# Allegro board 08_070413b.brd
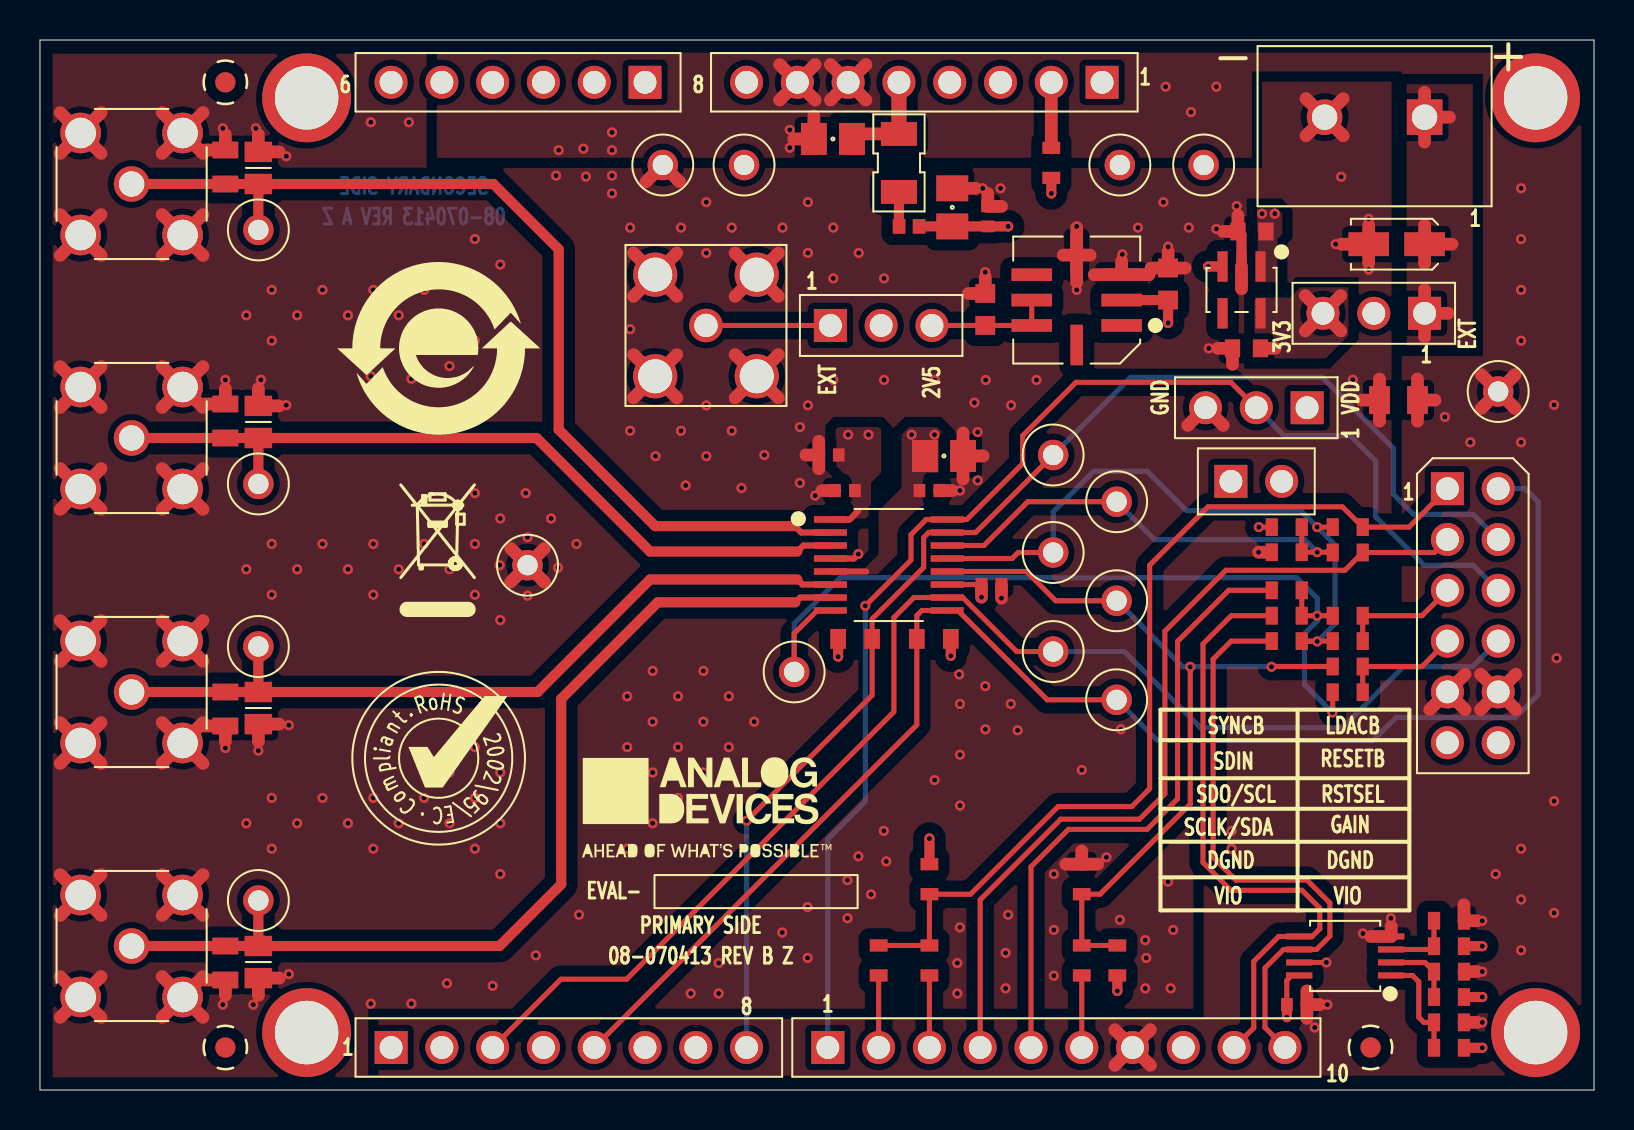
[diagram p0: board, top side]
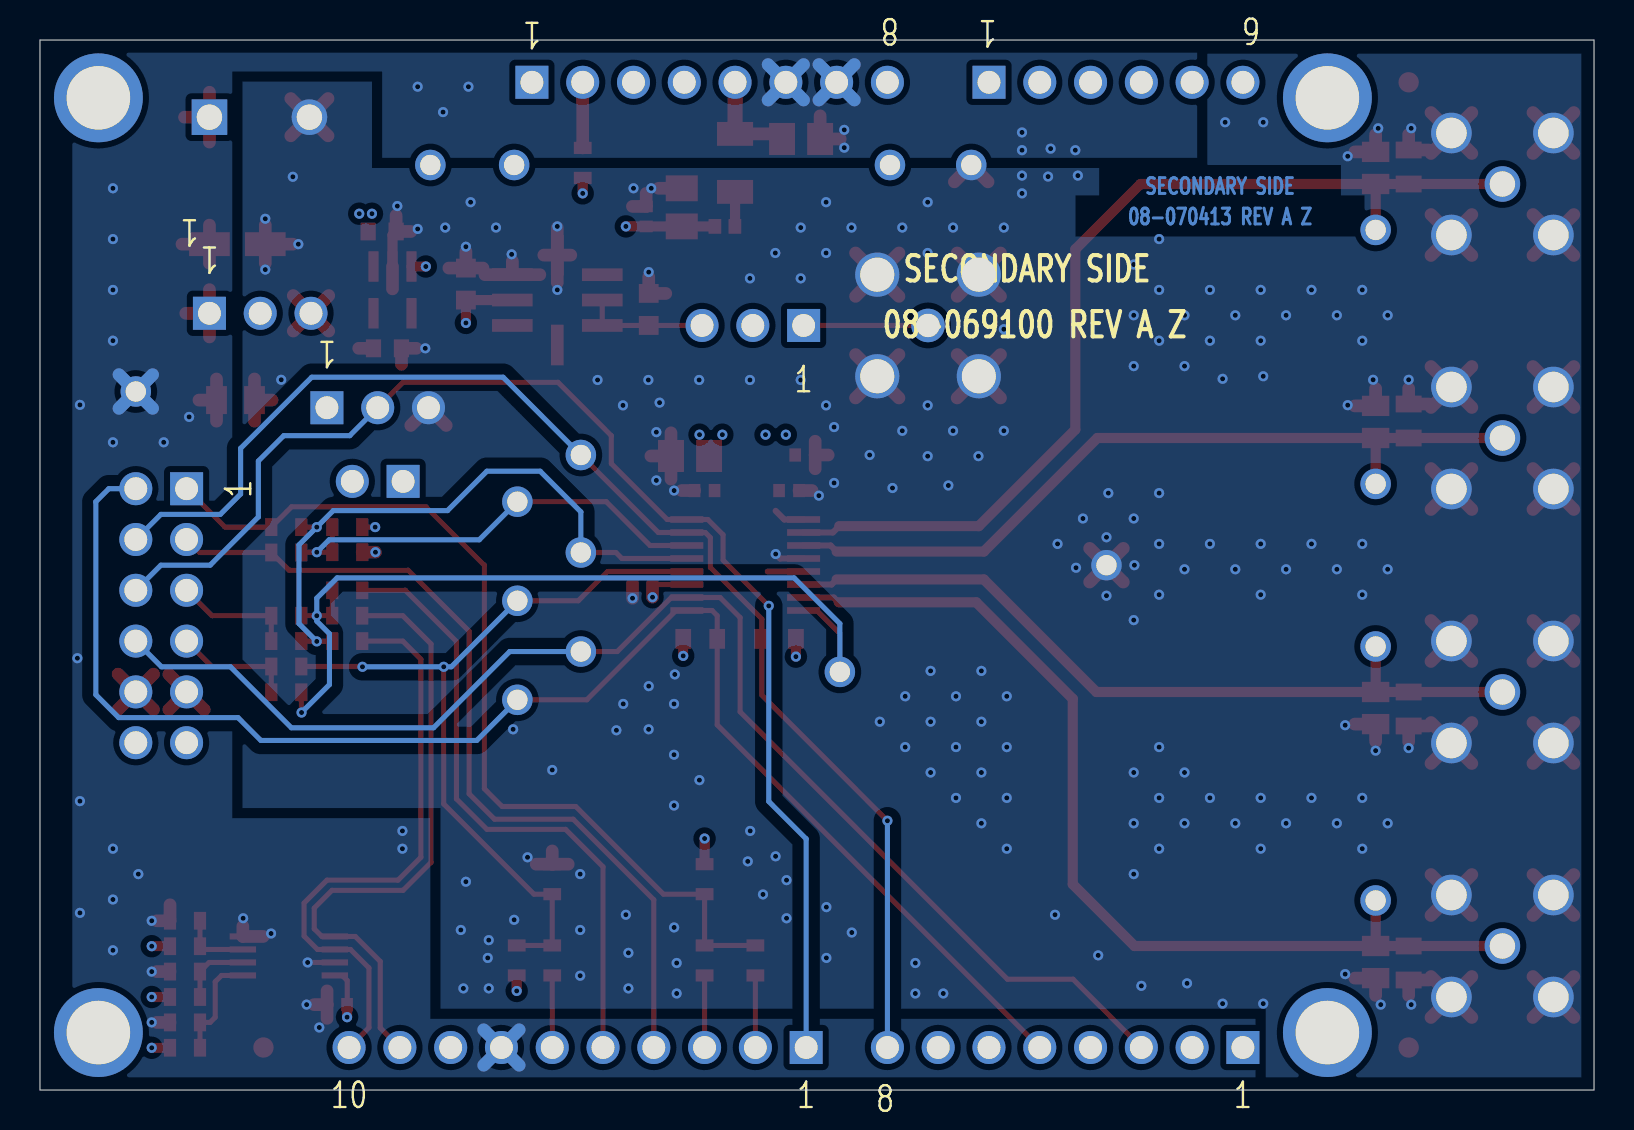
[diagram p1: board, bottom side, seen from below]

Outline 77.72 x 52.5 mm; copper layers: TOP, L2_GND, L3_PWR, BOTTOM. Coordinates in mm from the lower left corner of the outline.
Outline path: 0,52.5 77.72,52.5 77.72,0 0,0 0,52.5

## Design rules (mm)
constraint set DEFAULT: min track width 0.254

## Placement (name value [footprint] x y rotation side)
AGND  BLK  [CNKEY5001TP]  31.15 46.25 0 top
AGND1  BLK  [CNKEY5001TP]  24.38 26.24 0 top
C1  0.1uF  [C0402]  62.86 4.27 180 top
C2  10uF  [C0805H60]  39.66 47.55 180 top
C3  4.7uF  [C0805H60]  45.63 44.13 90 top
C4  0.1uF  [C0402]  47.41 43.68 90 top
C5  1uF  [C0603#2]  60.61 42.93 180 top
C6  0.1uF  [C0402]  44.48 29.97 0 top
C7  10uF  [C0805H60]  45.21 31.7 180 top
C8  10uF  [C3216]  67.85 42.29 180 top
C9  0.1uF  [C0402]  40.26 29.97 180 top
C10  0.1uF  [C0402]  39.45 31.75 180 top
C11  1uF  [C0603#2]  60.34 37.08 180 top
C12  0.1uF  [C0402]  47.59 25.27 0 top
C13  200pF  [C0805]  10.92 19.1 270 top
C14  200pF  [C0805]  10.92 33.4 90 top
C15  0.1uF  [C0603]  56.42 40.3 90 top
C16  200pF  [C0805]  10.92 46.1 90 top
C17  200pF  [C0805]  10.92 6.4 270 top
C18  1uF  [C0603]  47.28 39.03 90 top
DGND  BLK  [CNKEY5001TP]  72.93 34.92 0 top
E1  600OHM  [L1206H71]  42.96 46.35 270 top
EXT_REF  131-3701-261  [CNJOHNSON131-3701-261]  33.31 38.23 90 top
EXT_VDD  691102710002  [CNWURTH691102710002]  69.25 48.64 180 top
GAIN  WHT  [CNKEY5001TP]  50.67 21.92 0 top
LDACB  WHT  [CNKEY5001TP]  53.85 19.51 0 top
NOREF  -  []  77.72 0 0 top
NOREF#2  -  []  33.05 14.1 0 top
NOREF#3  -  []  217.08 56.1 0 top
NOREF#4  -  []  37.34 9.09 0 top
NOREF#5  -  []  19.68 23.71 0 top
NOREF#6  -  []  77.72 0 90 top
NOREF#7  -  []  -40.99 233.9 0 top
NOREF#8  -  []  0 0 0 top
NOREF#9  -  []  77.72 52.53 180 top
NOREF#10  -  []  0 0 0 top
NOREF#11  -  []  19.94 37.08 0 top
NOREF#12  -  []  0 52.5 270 top
NOREF#13  -  []  2.03 4.65 0 top
NOREF#14  -  []  0 52.5 0 top
NOREF#15  -  []  -68.29 -166.91 0 top
NOREF#16  -  [unnamed#2]  13.34 49.61 0 top
NOREF#17  -  []  -69.82 -166.91 0 top
NOREF#18  -  [unnamed#2]  74.8 2.87 0 top
NOREF#19  -  [unnamed#2]  74.8 49.61 0 top
NOREF#20  -  []  79.41 90.77 0 top
NOREF#21  -  []  0 52.5 0 top
NOREF#22  -  [unnamed#2]  66.55 2.12 0 top
NOREF#23  -  []  158.53 157.95 0 top
NOREF#24  -  []  19.94 16.59 0 top
NOREF#25  -  []  2.03 4.65 0 top
NOREF#26  -  [unnamed#2]  9.27 50.38 0 top
NOREF#27  -  []  77.72 0 90 top
NOREF#28  -  []  0 0 0 top
NOREF#29  -  []  -69.05 -166.91 0 top
NOREF#30  -  []  43.57 69.82 0 top
NOREF#31  -  [unnamed#2]  13.34 2.87 0 top
NOREF#32  -  [unnamed#2]  9.27 2.12 0 top
P3  SSQ-108-03-G-S  [CNSAMTECSSQ-108-XX-X-S]  53.12 50.38 180 top
P4  SSQ-106-03-G-S  [CNSAMTECSSQ-106-XX-X-S]  30.26 50.38 180 top
P6  SSQ-110-03-G-S  [CNSAMTECSSQ-110-XX-X-S]  39.4 2.12 0 top
P7  SSQ-108-03-G-S  [CNSAMTECSSQ-108-XX-X-S]  17.56 2.12 0 top
PMOD  TSW-106-08-G-D  [CNHDR2X6H330LD35]  70.39 30.06 270 top
R1  100K  [R0603]  70.47 7.19 180 top
R2  100K  [R0603]  70.47 5.92 0 top
R3  0  [R0805]  67.94 34.49 180 top
R4  100K  [R0603]  70.47 2.11 180 top
R5  0  [R0603]  50.58 46.35 270 top
R6  1.8  [R0402]  43.47 43.18 0 top
R7  100K  [R0603]  44.48 10.54 270 top
R8  100K  [R0603]  70.47 8.46 0 top
R9  100K  [R0603]  70.47 4.65 180 top
R10  0  [R0603]  44.48 6.48 270 top
R11  0  [R0603]  41.94 6.48 270 top
R12  100K  [R0603]  70.47 3.38 0 top
R13  2.0K  [R0805#2]  9.27 19.05 270 top
R14  2.0K  [R0805#2]  9.27 33.45 90 top
R15  2.0K  [R0805#2]  9.27 46.15 90 top
R16  2.0K  [R0805#2]  9.27 6.35 270 top
R17  0  [R0603]  62.36 24.98 0 top
R18  0  [R0603]  62.36 23.71 0 top
R19  0  [R0603]  65.41 19.89 180 top
R20  0  [R0603]  65.41 23.71 180 top
R21  0  [R0603]  65.41 26.87 180 top
R22  0  [R0603]  62.36 28.14 0 top
R23  0  [R0603]  62.36 26.89 0 top
R24  0  [R0603]  65.41 28.14 180 top
R25  0  [R0603]  62.36 22.44 0 top
R26  0  [R0603]  65.41 22.44 180 top
R27  0  [R0603]  52.1 6.48 90 top
R28  0  [R0603]  65.41 21.17 180 top
R29  0  [R0603]  53.88 6.48 90 top
R30  0  [R0603]  52.1 10.54 270 top
R31  100K  [R0603]  44.7 22.56 180 top
R32  100K  [R0603]  40.77 22.56 0 top
REF_SEL  YMC03SAAN  [CNTHMHDR1X3L300W100H343_A]  39.53 38.23 0 top
RESETB  WHT  [CNKEY5001TP]  50.67 31.75 0 top
RSTSEL  YMC03SAAN  [CNTHMHDR1X3L300W100H343_A]  63.37 34.11 180 top
SCLK/A0  WHT  [CNKEY5001TP]  53.85 24.46 180 top
SDIN/A1  WHT  [CNKEY5001TP]  53.85 29.41 0 top
SDO/SDA  WHT  [CNKEY5001TP]  37.72 20.91 0 top
SYNCB/SCL  WHT  [CNKEY5001TP]  50.67 26.87 180 top
U1  AD5686RBRUZ  [TSSOP16]  42.45 26.25 270 top
U2  ADP121-AUJZ33  [TSOT-5]  60.09 40 180 top
U3  ADR4525DEZ  [LCC8]  51.85 39.5 90 top
U4  24LC32A-I/MS  [MSOP8]  65.28 6.7 90 top
VDD  RED  [CNKEY5001TP]  58.2 46.25 0 top
VDD_SEL  YMC03SAAN  [CNTHMHDR1X3L300W100H343_A]  69.25 38.84 180 top
VDD_VIO  M20-9990245  [CNHARWIN-M20-9990246]  59.56 30.43 0 top
VLOGIC  RED  [CNKEY5001TP]  54.01 46.25 0 top
VOUT_A  1-1337482-0  [CNBNCSQ276H299]  4.58 32.6 0 top
VOUT_B  1-1337482-0  [CNBNCSQ276H299]  4.58 45.3 0 top
VOUT_C  1-1337482-0  [CNBNCSQ276H299]  4.58 19.9 0 top
VOUT_D  1-1337482-0  [CNBNCSQ276H299]  4.58 7.2 0 top
VOUTA  RED  [CNKEY5001TP]  10.92 30.3 0 top
VOUTB  RED  [CNKEY5001TP]  10.92 43 0 top
VOUTC  RED  [CNKEY5001TP]  10.92 22.18 0 top
VOUTD  RED  [CNKEY5001TP]  10.92 9.48 0 top
VREF  RED  [CNKEY5001TP]  35.21 46.25 90 top

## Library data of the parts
AGND DGND = CNTP1P: Tolerance: N/A; User Part Number: UPN; alternate symbols: (); part number: CNTP1P_TH-BLK,E005347,CNKEY5001TP; tolerance: N/A
AGND1 = CNTP1P: Tolerance: N/A; User Part Number: UPN; alternate symbols: (); part number: CNTP1P_TH-BLK,E019484,CNKEY5001TP; tolerance: N/A
C1 = CAP: User Part Number: UPN; Tolerance: 10; alternate symbols: (C0402L); part number: CAP_SM-0.1UF,16V,10,E028141,C0402; tolerance: 10
C2 C7 = CAP: Tolerance: 10; User Part Number: UPN; alternate symbols: (); part number: CAP_SM-10UF,25V,10,E014704,C0805H60; tolerance: 10
C3 = CAP: Tolerance: 10; User Part Number: UPN; alternate symbols: (); part number: CAP_SM-4.7UF,25V,10,E024738,C0805H60; tolerance: 10
C4 C6 C9 C10 C12 = CAP: User Part Number: UPN; Tolerance: 10; alternate symbols: (C0402L); part number: CAP_SM-0.1UF,16V,10,E018707,C0402; tolerance: 10
C5 C11 C18 = CAP: User Part Number: UPN; Tolerance: 10; alternate symbols: (C0603L); part number: CAP_SM-1UF,16V,10,E020111,C0603; tolerance: 10
C8 = CAPP: Tolerance: 10; User Part Number: UPN; alternate symbols: (); part number: CAPP_SM-10UF,10V,10,E011061,C3216; tolerance: 10
C13 C14 C16 C17 = CAP: User Part Number: UPN; Tolerance: 5; alternate symbols: (C0805L); part number: CAP_SM-200PF,16V,5,E034930,C0805; tolerance: 5
C15 = CAP: User Part Number: UPN; Tolerance: 10; alternate symbols: (C0603L); part number: CAP_SM-0.1UF,50V,10,E031401,C0603; tolerance: 10
E1 = FERRITE: User Part Number: UPN; Tolerance: 25; alternate symbols: (); part number: FERRITE_SM-600OHM,25,E048457,L1206H71; tolerance: 25
EXT_REF = CNBNC5P: Tolerance: N/A; User Part Number: UPN; alternate symbols: (); part number: CNBNC5P_TH-131-3701-261,E012123,CNJOHNSON131-3701-261; tolerance: N/A
EXT_VDD = CN2P: Tolerance: N/A; User Part Number: UPN; alternate symbols: (); part number: CN2P_TH-691102710002,E048111,CNWURTH691102710002; tolerance: N/A
GAIN LDACB RESETB SCLK/A0 SDIN/A1 SDO/SDA SYNCB/SCL = CNTP1P: Tolerance: N/A; User Part Number: UPN; alternate symbols: (); part number: CNTP1P_TH-WHT,E006153,CNKEY5001TP; tolerance: N/A
P3 P7 = CN8P_A: User Part Number: UPN; Tolerance: N/A; alternate symbols: (); part number: CN8P_A_TH-SSQ-108-03-G-S,E020478,CNSAMTECSSQ-108-XX-X-S; tolerance: N/A
P4 = CN6P: User Part Number: UPN; Tolerance: N/A; alternate symbols: (); part number: CN6P_TH-SSQ-106-03-G-S,E020477,CNSAMTECSSQ-106-XX-X-S; tolerance: N/A
P6 = CN10P: User Part Number: UPN; Tolerance: N/A; alternate symbols: (); part number: CN10P_TH-SSQ-110-03-G-S,E020479,CNSAMTECSSQ-110-XX-X-S; tolerance: N/A
PMOD = CN12P_V3: Tolerance: N/A; User Part Number: UPN; alternate symbols: (); part number: CN12P_V3_TH-TSW-106-08-G-D,E000735,CNHDR2X6H330LD35; tolerance: N/A
R1 R2 R4 R7-R9 R12 R31 R32 = RES: User Part Number: UPN; Tolerance: 1; alternate symbols: (R0603L); part number: RES_SM-100K,E018430,1/16W,1,R0603; tolerance: 1
R3 = RES: User Part Number: UPN; Tolerance: JUMPER; alternate symbols: (R0805L); part number: RES_SM-0,E030875,1/8W,JUMPER,R0805; tolerance: JUMPER
R5 R10 R11 R17-R30 = RES: User Part Number: UPN; Tolerance: JUMPER; alternate symbols: (R0603L); part number: RES_SM-0,E054377,1/10W,JUMPER,R0603; tolerance: JUMPER
R6 = RES: User Part Number: UPN; Tolerance: 5; alternate symbols: (R0402L); part number: RES_SM-1.8,E016361,1/10W,5,R0402; tolerance: 5
R13-R16 = RES: User Part Number: UPN; Tolerance: 0.1; alternate symbols: (R0805L); part number: RES_SM-2.0K,E003813,1/8W,0.1,R0805; tolerance: 0.1
REF_SEL RSTSEL VDD_SEL = CN3P_JMPRSHRT: User Part Number: UPN; Tolerance: N/A; alternate symbols: (); part number: CN3P_JMPRSHRT_TH-YMC03SAAN,E030075,CNTHMHDR1X3L300W100H343_A; tolerance: N/A
U1 = AD568XR_V4: Tolerance: N/A; User Part Number: UPN; alternate symbols: (); part number: AD568XR_V4_SM-AD5686RBRUZ,E012461,TSSOP16; tolerance: N/A
U2 = ADP121: User Part Number: UPN; Tolerance: N/A; alternate symbols: (); part number: ADP121_SM-ADP121-AUJZ33,E013943,TSOT-5; tolerance: N/A
U3 = ADR45XX_V2: User Part Number: UPN; Tolerance: N/A; alternate symbols: (); part number: ADR45XX_V2_SM-ADR4525DEZ,E055648,LCC8; tolerance: N/A
U4 = IC24FC256: Tolerance: N/A; User Part Number: UPN; alternate symbols: (); part number: IC24FC256_SM-24LC32A-I/MS,E014160,MSOP8; tolerance: N/A
VDD VLOGIC VOUTA VOUTB VOUTC VOUTD VREF = CNTP1P: Tolerance: N/A; User Part Number: UPN; alternate symbols: (); part number: CNTP1P_TH-RED,E016323,CNKEY5001TP; tolerance: N/A
VDD_VIO = CN2P: Tolerance: N/A; User Part Number: UPN; alternate symbols: (); part number: CN2P_TH-M20-9990245,E019487,CNHARWIN-M20-9990246; tolerance: N/A
VOUT_A VOUT_B VOUT_C VOUT_D = CNBNC5P: Tolerance: N/A; User Part Number: UPN; alternate symbols: (); part number: CNBNC5P_TH-1-1337482-0,E013941,CNBNCSQ276H299; tolerance: N/A

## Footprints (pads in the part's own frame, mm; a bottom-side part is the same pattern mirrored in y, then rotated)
C0402
  rect 0.584x0.66 smd: 1(-0.5,0) 2(0.5,0)
C0603
  rect 0.94x0.991 smd: 1(-0.8,0) 2(0.8,0)
C0603#2
  rect 0.762x0.889 smd: 1(-0.7,0) 2(0.7,0)
C0805
  rect 1.016x1.372 smd: 1(-0.803,0) 2(0.803,0)
C0805H60
  rect 1.295x1.6 smd: 1(-0.953,0) 2(0.953,0)
C3216
  rect 2.032x1.194 smd: N(1.397,0) P(-1.397,0)
CNBNCSQ276H299
  round 1.778 hole 1.27: 1(0,0)
  round 2.032 hole 1.524: 2(-2.55,2.55) 3(2.55,2.55) 4(2.55,-2.55) 5(-2.55,-2.55)
CNHARWIN-M20-9990246
  rect 1.651x1.651 hole 1.143: 1(0,0)
  round 1.651 hole 1.143: 2(2.54,0)
CNHDR2X6H330LD35
  rect 1.651x1.651 hole 1.143: 1(0,0)
  round 1.651 hole 1.143: 2(2.54,0) 3(5.08,0) 4(7.62,0) 5(10.16,0) 6(12.7,0) 7(0,2.54) 8(2.54,2.54) 9(5.08,2.54) 10(7.62,2.54) 11(10.16,2.54) 12(12.7,2.54)
CNJOHNSON131-3701-261
  round 1.676 hole 1.168: 1(0,0)
  round 2.21 hole 1.702: 2(-2.54,2.54) 3(2.54,2.54) 4(2.54,-2.54) 5(-2.54,-2.54)
CNKEY5001TP
  round 1.524 hole 1.016: 1(0,0)
CNSAMTECSSQ-106-XX-X-S
  rect 1.651x1.651 hole 1.143: 1(0,0)
  round 1.651 hole 1.143: 2(2.54,0) 3(5.08,0) 4(7.62,0) 5(10.16,0) 6(12.7,0)
CNSAMTECSSQ-108-XX-X-S
  rect 1.651x1.651 hole 1.143: 1(0,0)
  round 1.651 hole 1.143: 2(2.54,0) 3(5.08,0) 4(7.62,0) 5(10.16,0) 6(12.7,0) 7(15.24,0) 8(17.78,0)
CNSAMTECSSQ-110-XX-X-S
  rect 1.651x1.651 hole 1.143: 1(0,0)
  round 1.651 hole 1.143: 2(2.54,0) 3(5.08,0) 4(7.62,0) 5(10.16,0) 6(12.7,0) 7(15.24,0) 8(17.78,0) 9(20.32,0) 10(22.86,0)
CNTHMHDR1X3L300W100H343_A
  rect 1.651x1.651 hole 1.143: 1(0,0)
  round 1.651 hole 1.143: 2(2.54,0) 3(5.08,0)
CNWURTH691102710002
  rect 1.778x1.778 hole 1.27: 1(0,0)
  round 1.778 hole 1.27: 2(5,0)
L1206H71
  rect 1.194x1.803 smd: 1(-1.45,0) 2(1.45,0)
LCC8
  rect 0.635x2.032 smd: 1(-1.27,-2.248) 2(0,-2.248) 3(1.27,-2.248) 5(1.27,2.248) 6(0,2.248) 7(-1.27,2.248)
  rect 2.032x0.635 smd: 4(2.248,0) 8(-2.248,0)
MSOP8
  rect 0.305x1.321 smd: 1(-0.975,-2.3) 2(-0.325,-2.3) 3(0.325,-2.3) 4(0.975,-2.3) 5(0.975,2.3) 6(0.325,2.3) 7(-0.325,2.3) 8(-0.975,2.3)
R0402
  rect 0.635x0.737 smd: 1(-0.5,0) 2(0.5,0)
R0603
  rect 0.61x0.889 smd: 1(-0.75,0) 2(0.75,0)
R0805
  rect 1.041x1.397 smd: 1(-0.95,0) 2(0.95,0)
R0805#2
  rect 0.838x1.295 smd: 1(-0.85,0) 2(0.85,0)
TSOT-5
  rect 0.508x1.524 smd: 1(-0.95,-1.17) 2(0,-1.17) 3(0.95,-1.17) 4(0.95,1.17) 5(-0.95,1.17)
TSSOP16
  rect 0.33x1.651 smd: 1(-2.275,-2.92) 2(-1.625,-2.92) 3(-0.975,-2.92) 4(-0.325,-2.92) 5(0.325,-2.92) 6(0.975,-2.92) 7(1.625,-2.92) 8(2.275,-2.92) 9(2.275,2.92) 10(1.625,2.92) 11(0.975,2.92) 12(0.325,2.92) 13(-0.325,2.92) 14(-0.975,2.92) 15(-1.625,2.92) 16(-2.275,2.92)
unnamed#2
  round 4.445 hole 3.175 unplated: (0,0)

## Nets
AGND: AGND.1(N1) AGND1.1(N1) C3.2(N2) C4.2(N2) C5.2(N2) C6.2(N2) C7.1 C8.N(N2) C9.2(N2) C10.2(N2) C11.2(N2) C12.2(N2) C13.2(N2) C14.2(N2) C15.2(N2) C16.2(N2) C17.2(N2) C18.2(N2) EXT_REF.2 EXT_REF.3 EXT_REF.4 EXT_REF.5(SH4) EXT_VDD.2(N2) R3.2(N2) R13.2(N2) R14.2(N2) R15.2(N2) R16.2(N2) R23.1 R30.1 RSTSEL.3(S3) U1.4 U2.2 U3.3 U3.4 VOUT_A.2 VOUT_A.3 VOUT_A.4 VOUT_A.5(SH4) VOUT_B.2 VOUT_B.3 VOUT_B.4 VOUT_B.5(SH4) VOUT_C.2 VOUT_C.3 VOUT_C.4 VOUT_C.5(SH4) VOUT_D.2 VOUT_D.3 VOUT_D.4 VOUT_D.5(SH4)
DGND: C1.1 C2.2(N2) DGND.1(N1) P3.6 P3.7 P6.7 PMOD.5 PMOD.11 R2.2(N2) R3.1 R8.2(N2) R12.2(N2) U4.4 U4.7(WP)
VBUS_USB: C3.1 C4.1 C5.1 R6.2(N2) U2.1 U2.3
VDD_EXT: C8.P EXT_VDD.1 VDD_SEL.1
ARD_SCL: P6.10 R25.1 U4.6
ARD_SCLK: P6.6 R27.1
ARD_SDA: P6.9(N9) R18.1 U4.5
ARD_SDIN: P6.4 PMOD.2 R21.1
ARD_SDO: P6.5 R17.1
DAC_GAIN: GAIN.1(N1) P7.3 PMOD.10 U1.10
DAC_LDACB: LDACB.1(N1) P7.5 PMOD.7 R31.2(N2) U1.9
DAC_OUTA: C14.1 R14.1 U1.3 VOUT_A.1 VOUTA.1(N1)
DAC_OUTB: C16.1 R15.1 U1.2 VOUT_B.1 VOUTB.1(N1)
DAC_OUTC: C13.1 R13.1 U1.6 VOUT_C.1 VOUTC.1(N1)
DAC_OUTD: C17.1 R16.1 U1.7 VOUT_D.1 VOUTD.1(N1)
DAC_RESETB: P7.8(N8) PMOD.8 R32.2(N2) RESETB.1(N1) U1.15
DAC_RSTSEL: P6.1 PMOD.9 RSTSEL.2 U1.16
DAC_SCLK/A0: R27.2(N2) R28.2(N2) R29.2(N2) R30.2(N2) SCLK/A0.1(N1) U1.12
DAC_SDIN/A1: R21.2(N2) R22.2(N2) R23.2(N2) SDIN/A1.1(N1) U1.14
DAC_SDO/SDA: R17.2(N2) R18.2(N2) R19.2(N2) R20.2(N2) SDO/SDA.1(N1) U1.8
DAC_SYNCB: PMOD.1 R7.2(N2) R10.1 R11.1 R24.1
DAC_SYNCB/SCL: R24.2(N2) R25.2(N2) R26.2(N2) SYNCB/SCL.1(N1) U1.13
DAC_VDD: C6.1 C7.2(N2) C15.1 U1.5 U3.2 VDD.1(N1) VDD_SEL.2 VDD_VIO.1
DAC_VLOGIC: C1.2(N2) C12.1 PMOD.6 PMOD.12(VCC2) R1.1 R4.1 R5.2(N2) R7.1 R9.1 R22.1 R29.1 R31.1 R32.1 RSTSEL.1 U1.11 U4.8 VDD_VIO.2(N2) VLOGIC.1(N1)
DAC_VREF: C9.1 C10.1 REF_SEL.2 U1.1(VREF) VREF.1(N1)
LDO_3V3: C11.1 U2.5(VOUT) VDD_SEL.3(S3)
PMOD_SCLK/SDA: PMOD.4 R19.1 R28.1
PMOD_SDO/SCL: PMOD.3 R20.1 R26.1
UNNAMED_3_CAP_I47_N1: C2.1 E1.1 P3.5
UNNAMED_3_CN8PA_I4_N2: P3.2 R5.1
UNNAMED_3_CN10P_I1_N2: P6.2 R11.2(N2)
UNNAMED_3_CN10P_I1_N3: P6.3 R10.2(N2)
UNNAMED_3_FERRITE_I48_N2: E1.2(N2) R6.1
UNNAMED_3_IC24FC256_I22_A1: R2.1 R9.2(N2) U4.2
UNNAMED_3_IC24FC256_I22_A2: R1.2(N2) R8.1 U4.3
UNNAMED_3_RES_I15_N1: R4.2(N2) R12.1 U4.1
VREF_2V5: C18.1 REF_SEL.3(S3) U3.6(VOUTSENSE) U3.7
VREF_EXT: EXT_REF.1 REF_SEL.1

Pads without a net: P3 1 3 4 8; P4 1 2 3 4 5 6; P6 8; P7 1 2 4 6 7; U2 4; U3 1 5 8

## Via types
v1: diameter 0.508, hole 0.254, TOP to BOTTOM, 263 vias

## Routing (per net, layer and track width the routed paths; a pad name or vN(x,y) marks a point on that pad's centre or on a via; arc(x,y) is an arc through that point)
AGND: length 184.8
  TOP w0.305: U1.4 40.71,26.58 v1(40.93,26.8)
  TOP w0.508: C5.2 60.09,42.75 U2.2
  TOP w0.635: C7.1 46.16,32.86 ; C7.1 46.16,30.54 ; C7.1 47.17,31.7 ; VOUT_C.5 3.05,16.33 ; VOUT_C.5 1.01,18.37 ; VOUT_C.5 3.05,18.37 ; VOUT_C.5 1.01,16.33 ; 6.11,29.03 VOUT_A.4 ; VOUT_A.4 8.15,31.07 ; VOUT_A.4 6.11,31.07 ; VOUT_A.4 8.15,29.03 ; EXT_REF.4 36.93,39.68 ; EXT_REF.4 34.76,39.68 ; EXT_REF.4 36.93,41.85 ; EXT_REF.4 34.76,41.85 ; 60.09,40.06 U2.2 ; C8.N 66.46,43.24 ; C8.N 66.46,41.34 ; C8.N 65.08,42.29 ; 39.11,29.97 C9.2 ; 1.01,36.17 VOUT_A.2 ; VOUT_A.2 3.05,34.13 ; VOUT_A.2 1.01,34.13 ; VOUT_A.2 3.05,36.17 ; EXT_REF.5 36.93,36.77 ; EXT_REF.5 36.93,34.6 ; EXT_REF.5 34.76,34.6 ; EXT_REF.5 34.76,36.77 ; 29.68,39.68 EXT_REF.3 ; EXT_REF.3 31.85,41.85 ; EXT_REF.3 29.68,41.85 ; EXT_REF.3 31.85,39.68 ; VOUT_D.5 3.05,3.63 ; VOUT_D.5 1.01,5.67 ; VOUT_D.5 1.01,3.63 ; VOUT_D.5 3.05,5.67 ; 1.01,41.73 VOUT_B.5 ; VOUT_B.5 1.01,43.77 ; VOUT_B.5 3.05,41.73 ; VOUT_B.5 3.05,43.77 ; 10.92,47.77 C16.2 11.96,46.91 ; EXT_REF.2 31.85,34.6 ; EXT_REF.2 31.85,36.77 ; EXT_REF.2 29.68,34.6 ; EXT_REF.2 29.68,36.77 ; 51.85,40.37 U3.4 ; U3.4 51.85,43.12 ; U3.4 52.52,41.74 ; U3.4 51.18,41.74 ; v1(48.09,24.59) C12.2 ; VOUT_A.3 8.15,34.13 ; VOUT_A.3 6.11,34.13 ; VOUT_A.3 6.11,36.17 ; VOUT_A.3 8.15,36.17 ; 8.27,47 R15.2 9.27,47.77 ; 59.18,33.23 RSTSEL.3 57.41,33.23 ; 58.91,37.08 C11.2 59.64,36.28 ; R30.1 52.1,11.95 ; R30.1 52.9,11.29 ; R30.1 51.3,11.29 ; 6.11,48.87 VOUT_B.3 ; VOUT_B.3 8.15,46.83 ; VOUT_B.3 8.15,48.87 ; VOUT_B.3 6.11,46.83 ; VOUT_B.2 3.05,48.87 ; VOUT_B.2 1.01,48.87 ; VOUT_B.2 3.05,46.83 ; VOUT_B.2 1.01,46.83 ; VOUT_A.5 3.05,31.07 ; VOUT_A.5 1.01,31.07 ; VOUT_A.5 1.01,29.03 ; VOUT_A.5 3.05,29.03 ; 1.01,21.43 VOUT_C.2 ; VOUT_C.2 1.01,23.47 ; VOUT_C.2 3.05,23.47 ; VOUT_C.2 3.05,21.43 ; VOUT_C.3 8.15,23.47 ; VOUT_C.3 8.15,21.43 ; VOUT_C.3 6.11,23.47 ; VOUT_C.3 6.11,21.43 ; 10.92,4.73 C17.2 11.96,5.59 ; 47.28,40.65 C18.2 46.43,39.83 ; 38.95,31.06 C10.2 ; C10.2 38.95,32.44 ; C10.2 38.3,31.75 ; EXT_VDD.2 65.18,49.57 ; EXT_VDD.2 65.18,47.71 ; EXT_VDD.2 63.32,49.57 ; EXT_VDD.2 63.32,47.71 ; U3.3 55.47,40.77 ; U3.3 52.73,40.77 ; U3.3 54.1,41.44 ; 11.96,34.21 C14.2 10.92,35.07 ; VOUT_C.4 8.15,16.33 ; VOUT_C.4 6.11,16.33 ; VOUT_C.4 8.15,18.37 ; VOUT_C.4 6.11,18.37 ; VOUT_D.4 8.15,3.63 ; VOUT_D.4 6.11,5.67 ; VOUT_D.4 6.11,3.63 ; VOUT_D.4 8.15,5.67 ; 66.12,34.49 R3.2 ; R3.2 67,33.44 ; R3.2 67,35.55 ; 1.01,8.73 VOUT_D.2 ; VOUT_D.2 1.01,10.77 ; VOUT_D.2 3.05,10.77 ; VOUT_D.2 3.05,8.73 ; 23.54,25.4 AGND1.1 ; AGND1.1 25.23,27.08 ; AGND1.1 25.23,25.4 ; AGND1.1 23.54,27.08 ; 8.27,5.5 R16.2 9.27,4.72 ; v1(60.95,26.89) R23.1 ; 31.99,45.41 AGND.1 30.31,45.41 ; VOUT_D.3 8.15,8.73 ; VOUT_D.3 6.11,10.77 ; VOUT_D.3 6.11,8.73 ; VOUT_D.3 8.15,10.77 ; 9.27,35.07 R14.2 8.27,34.3 ; C3.2 46.78,45.08 ; 9.27,17.42 R13.2 8.27,18.2 ; VOUT_B.4 8.15,41.73 ; VOUT_B.4 6.11,43.77 ; VOUT_B.4 6.11,41.73 ; VOUT_B.4 8.15,43.77 ; 48.09,44.18 C4.2 47.41,44.83 ; C6.2 45.63,29.97 ; 55.57,41.1 C15.2 ; C15.2 56.42,41.92 ; C15.2 57.27,41.1 ; 11.96,18.29 C13.2 10.92,17.43 ; 59.91,43.73 C5.2 59.18,42.93
  vias: v1(9.14,48.08) v1(9.14,4.27) v1(9.27,35.51) v1(9.27,17.1) v1(10.32,38.73) v1(10.32,26.04) v1(10.32,13.34) v1(10.67,4.27) v1(10.79,48.08) v1(10.92,16.97) v1(11.05,35.51) v1(11.59,40) v1(11.59,37.46) v1(11.59,27.3) v1(11.59,24.77) v1(11.59,14.61) v1(11.59,12.06) v1(12.32,46.69) v1(12.32,34.24) v1(12.45,18.24) v1(12.45,5.79) v1(12.86,38.73) v1(12.86,26.04) v1(12.86,13.34) v1(14.13,40) v1(14.13,27.3) v1(14.13,14.61) v1(15.4,38.73) v1(15.4,26.04) v1(15.4,13.34) v1(16.54,48.39) v1(16.54,35.69) v1(16.54,4.32) v1(16.67,40) v1(16.67,37.46) v1(16.67,27.3) v1(16.67,24.77) v1(16.67,14.61) v1(16.67,12.06) v1(17.94,38.73) v1(17.94,26.04) v1(17.94,13.34) v1(18.45,48.39) v1(18.58,35.56) v1(18.58,4.32) v1(19.21,40) v1(19.21,37.46) v1(19.21,27.3) v1(19.21,14.61) v1(20.35,5.33) v1(20.48,38.73) v1(20.48,36.2) v1(20.48,26.04) v1(20.48,15.88) v1(20.48,13.34) v1(21.75,42.54) v1(21.75,40) v1(21.75,37.46) v1(21.75,29.85) v1(21.75,27.3) v1(21.75,24.77) v1(21.75,17.14) v1(21.75,14.61) v1(21.75,12.06) v1(22.64,5.21) v1(23.02,41.27) v1(23.02,38.73) v1(23.02,36.2) v1(23.02,28.57) v1(22.99,26.24) v1(23.02,23.5) v1(23.02,15.88) v1(23.02,13.34) v1(23.02,10.79) v1(24.29,29.85) v1(24.38,27.64) v1(24.38,24.72) v1(24.8,6.73) v1(25.56,28.57) v1(25.82,45.72) v1(25.91,26.11) v1(26.83,27.3) v1(26.96,8.76) v1(27.3,45.67) v1(28.61,45.72) v1(28.61,44.83) v1(29.37,19.68) v1(29.37,17.14) v1(29.37,14.61) v1(29.37,12.06) v1(29.52,43.12) v1(29.52,38.04) v1(29.52,32.96) v1(30.64,20.96) v1(30.64,18.41) v1(30.64,15.88) v1(30.64,13.34) v1(30.79,31.69) v1(31.91,19.68) v1(31.91,17.14) v1(31.91,14.61) v1(32.06,43.12) v1(32.06,32.96) v1(32.29,30.23) v1(32.55,4.83) v1(33.18,20.96) v1(33.18,18.41) v1(33.18,15.88) v1(33.33,44.39) v1(33.33,41.85) v1(33.33,34.23) v1(33.33,31.69) v1(33.94,6.35) v1(33.94,4.83) v1(34.45,19.68) v1(34.45,17.14) v1(34.6,43.12) v1(34.6,32.96) v1(35.09,30.1) v1(35.72,18.41) v1(36.23,31.75) v1(37.14,43.12) v1(37.12,7.87) v1(38.01,33.15) v1(38.01,30.35) v1(38.41,44.39) v1(38.41,41.85) v1(38.41,34.23) v1(38.39,9.14) v1(38.39,6.6) v1(38.77,29.72) v1(39.68,43.12) v1(39.68,40.58) v1(39.68,35.5) v1(40.39,10.49) v1(40.39,8.59) v1(40.95,41.85) v1(40.93,11.68) v1(41.56,9.78) v1(42.22,40.58) v1(42.22,35.5) v1(42.2,12.95) v1(42.33,11.43) v1(44.76,35.5) v1(44.74,15.49) v1(45.88,6.35) v1(45.88,4.83) v1(45.97,20.78) v1(46.01,29.97) v1(46.01,19.3) v1(46.01,16.76) v1(46.01,14.22) v1(46.01,8.13) v1(46.74,34.37) v1(46.9,32.89) v1(46.9,30.48) v1(47.15,45.08) v1(47.28,40.89) v1(47.28,20.19) v1(47.3,35.5) v1(47.28,18.03) v1(48.04,45.08) v1(48.29,6.86) v1(48.29,5.08) v1(48.42,8.76) v1(48.57,34.23) v1(48.55,19.3) v1(48.89,17.98) v1(49.84,35.5) v1(50.71,10.79) v1(50.71,8) v1(50.71,5.71) v1(51.85,43.18) v1(51.85,40) v1(52.1,16) v1(53.34,11.63) v1(54.06,18.03) v1(54.01,8.51) v1(54.14,41.78) v1(54.92,43.12) v1(55.28,7.49) v1(55.28,5.08) v1(55.33,6.6) v1(56.19,44.39) v1(56.42,42.16) v1(56.42,10.41) v1(56.55,5.08) v1(56.68,8) v1(57.46,43.12) v1(58.45,37.08) v1(58.84,43.05) v1(59.85,44.2) v1(64.8,42.29) v1(65.08,45.66) v1(65.66,35.51) v1(66.46,43.56) v1(66.46,41.02)
DGND: length 96
  TOP w0.254: U4.7 v1(64.34,6.38)
  TOP w0.635: 63.37,4.27 63.37,4.96 ; 63.37,4.27 63.37,3.58 ; 63.37,4.27 64.01,4.27 ; R2.2 71.88,5.92 ; P3.6 41.31,49.5 ; P3.6 41.31,51.27 ; P3.6 39.53,51.27 ; P3.6 39.53,49.5 ; 69.51,19.02 PMOD.5 ; PMOD.5 71.28,19.02 ; PMOD.5 71.28,20.79 ; PMOD.11 73.82,20.79 ; PMOD.11 72.05,19.02 ; PMOD.11 73.82,19.02 ; PMOD.11 72.05,20.79 ; 38.71,48.71 C2.2 37.7,47.55 ; 72.09,35.77 DGND.1 ; DGND.1 73.77,34.08 ; DGND.1 73.77,35.77 ; DGND.1 72.09,34.08 ; R3.1 68.89,35.55 ; R3.1 69.77,34.49 ; R3.1 68.89,33.44 ; 53.76,3.01 P6.7 ; P6.7 55.53,1.24 ; P6.7 53.76,1.24 ; P6.7 55.53,3.01 ; 36.99,49.5 P3.7 ; P3.7 38.77,51.27 ; P3.7 36.99,51.27 ; P3.7 38.77,49.5 ; 67.58,8.19 U4.4 66.56,7.68 ; R12.2 71.88,3.38 ; 71.22,9.26 R8.2 71.88,8.46
  L2_GND w0.635: DGND.1 73.77,35.77 ; DGND.1 72.09,35.77 ; DGND.1 73.77,34.08 ; DGND.1 72.09,34.08 ; P3.7 38.77,49.5 ; P3.7 36.99,49.5 ; P3.7 36.99,51.27 ; P3.7 38.77,51.27 ; 69.51,20.79 PMOD.5 ; PMOD.5 71.28,20.79 ; PMOD.5 71.28,19.02 ; PMOD.5 69.51,19.02 ; P6.7 55.53,1.24 ; P6.7 53.76,1.24 ; P6.7 53.76,3.01 ; P6.7 55.53,3.01 ; P3.6 41.31,49.5 ; P3.6 39.53,51.27 ; P3.6 39.53,49.5 ; P3.6 41.31,51.27 ; PMOD.11 73.82,19.02 ; PMOD.11 72.05,19.02 ; PMOD.11 72.05,20.79 ; PMOD.11 73.82,20.79
  L3_PWR w0.635: 53.76,3.01 P6.7 ; P6.7 55.53,3.01 ; P6.7 55.53,1.24 ; P6.7 53.76,1.24
  BOTTOM w0.635: 39.53,49.5 P3.6 ; P3.6 41.31,51.27 ; P3.6 41.31,49.5 ; P3.6 39.53,51.27 ; P3.7 38.77,51.27 ; P3.7 38.77,49.5 ; P3.7 36.99,49.5 ; P3.7 36.99,51.27 ; 53.76,3.01 P6.7 ; P6.7 55.53,1.24 ; P6.7 53.76,1.24 ; P6.7 55.53,3.01 ; 72.09,34.08 DGND.1 ; DGND.1 72.09,35.77 ; DGND.1 73.77,35.77 ; DGND.1 73.77,34.08
  vias: v1(25.94,46.99) v1(27.18,47.07) v1(28.61,47.88) v1(28.61,46.99) v1(37.5,48.01) v1(37.5,47.12) v1(56.3,50.16) v1(57.57,48.89) v1(58.84,50.16) v1(59.6,12.95) v1(59.6,12.06) v1(63.75,3.13) v1(64.39,4.27) v1(66.17,7.82) v1(67.56,8.59) v1(70.27,33.66) v1(71.54,32.38) v1(72.14,8.46) v1(72.14,5.92) v1(72.14,3.38) v1(72.81,10.79) v1(74.08,45.08) v1(74.08,42.54) v1(74.08,40) v1(74.08,37.46) v1(74.08,32.38) v1(74.08,12.06) v1(74.08,9.53) v1(74.08,6.98) v1(75.73,34.26) v1(75.73,14.44) v1(75.73,8.86) v1(75.85,21.59)
VBUS_USB: length 5.2
  TOP w0.508: R6.2 C3.1 C4.1 v1(48.42,43.18) ; U2.3 v1(58.43,41.17)
  vias: v1(61.12,43.81) v1(61.76,43.81)
VDD_EXT: length 10.6
  TOP w0.635: EXT_VDD.1 69.25,49.89 ; EXT_VDD.1 69.25,47.4 ; EXT_VDD.1 70.49,48.64 ; C8.P 69.25,43.24 ; C8.P 70.62,42.29 ; C8.P 69.25,41.34 ; 69.25,37.65 VDD_SEL.1 ; VDD_SEL.1 69.25,40.02 ; VDD_SEL.1 70.43,38.84
ARD_SCL: length 29.9
  TOP w0.254: P6.10 61.27,3.12 61.27,6.1 62.19,7.03 U4.6 63.85,7.03 64.52,7.7 64.52,9.35 63.37,10.49 59.82,10.49 58.67,11.63 58.67,21.54 59.58,22.44 R25.1
ARD_SCLK: length 3.6
  TOP w0.254: R27.1 P6.6
ARD_SDA: length 31.5
  TOP w0.254: P6.9 60.71,3.11 60.71,6.43 61.96,7.68 U4.5 63.63,7.68 64.01,8.06 64.01,9.09 63.12,9.98 59.56,9.98 58.17,11.38 58.17,22.3 59.58,23.71 R18.1
ARD_SDIN: length 43
  TOP w0.254: P6.4 47.02,9.51 51.05,13.54 54.99,13.54 56.26,14.81 56.26,22.94 59.31,25.99 65.27,25.99 R21.1 69.74,26.87 PMOD.2
ARD_SDO: length 31.4
  TOP w0.254: P6.5 49.56,11.16 51.44,13.03 55.37,13.03 56.9,14.56 56.9,22.43 59.45,24.98 R17.1
DAC_GAIN: length 66.9
  TOP w0.254: P7.3 26.05,5.54 29.34,5.54 42.71,18.91 42.71,23.62 43.71,24.62 U1.10 46.15,24.62 48.85,21.92 GAIN.1
  BOTTOM w0.254: PMOD.10 71.65,21.16 68.2,21.16 65.15,18.11 58.04,18.11 54.23,21.92 GAIN.1
DAC_LDACB: length 75
  TOP w0.254: P7.5 43.85,18.26 R31.2 43.85,23.72 44.11,23.97 U1.9 45.91,23.97 50.38,19.51 LDACB.1
  BOTTOM w0.254: LDACB.1 55.88,17.48 66.67,17.48 67.82,18.62 73.79,18.62 74.93,19.76 74.93,29.41 74.28,30.06 PMOD.7
DAC_OUTA: length 39.7
  TOP w0.305: U1.3 38.18,27.22 37.88,26.92
  TOP w0.508: C14.1 R14.1 VOUT_A.1 ; C14.1 VOUTA.1 ; C14.1 24.84,32.6 30.51,26.92 37.88,26.92
DAC_OUTB: length 49.7
  TOP w0.305: U1.2 38.07,27.87 37.75,28.19
  TOP w0.508: C16.1 R15.1 VOUT_B.1 ; C16.1 22.68,45.3 25.94,42.04 25.94,33.02 30.77,28.19 37.75,28.19 ; C16.1 VOUTB.1
DAC_OUTC: length 39.7
  TOP w0.305: U1.6 38.13,25.27 37.88,25.53
  TOP w0.508: C13.1 VOUTC.1 ; C13.1 24.89,19.9 30.51,25.53 37.88,25.53 ; C13.1 R13.1 VOUT_C.1
DAC_OUTD: length 49.9
  TOP w0.305: 37.78,24.38 38.02,24.62 U1.7
  TOP w0.508: C17.1 22.98,7.2 26.07,10.29 26.07,19.56 30.9,24.38 37.78,24.38 ; C17.1 VOUTD.1 ; C17.1 R16.1 VOUT_D.1
DAC_RESETB: length 65.9
  TOP w0.254: v1(35.34,13.46) 41.62,19.74 R32.2 41.62,23.55 44.2,26.13 44.2,27.62 44.45,27.87 U1.15 46.8,27.87 RESETB.1
  BOTTOM w0.254: RESETB.1 54.56,35.64 64.14,35.64 67.69,32.08 67.69,29.8 68.71,28.78 71.68,28.78 PMOD.8 ; P7.8 v1(35.34,13.46)
DAC_RSTSEL: length 66.7
  TOP w0.254: RSTSEL.2 59.56,35.38 51.82,35.38 49.15,32.72 49.15,31.32 46.35,28.52 U1.16 44.32,28.52 43.56,27.76 43.56,26.49 v1(41.28,24.21)
  BOTTOM w0.254: v1(41.28,24.21) 41.28,14.43 39.4,12.56 P6.1 ; RSTSEL.2 62.23,32.72 65.53,32.72 66.8,31.45 66.8,28.65 69.22,26.24 71.68,26.24 PMOD.9
DAC_SCLK/A0: length 39.8
  TOP w0.254: R28.2 61.61,21.17 v1(61.59,21.16) ; R29.2 R27.2 R30.2 53.02,9.79 57.53,14.3 v1(57.53,21.16) ; U1.12 49.34,25.92 50.8,24.46 SCLK/A0.1
  BOTTOM w0.254: v1(61.59,21.16) v1(57.53,21.16) 57.15,21.16 SCLK/A0.1
DAC_SDIN/A1: length 23.3
  TOP w0.254: 63.13,26.89 v1(63.88,26.89) 64.64,26.89 R21.2 ; 63.13,26.89 63.12,26.9 R23.2 ; 63.13,26.89 R23.2 ; R23.2 R22.2 ; SDIN/A1.1 49.4,29.41 47.21,27.22 U1.14
  BOTTOM w0.254: SDIN/A1.1 55.75,27.51 63.26,27.51 v1(63.88,26.89)
DAC_SDO/SDA: length 44.5
  TOP w0.254: v1(64.64,18.87) 64.65,18.89 R19.2 ; R17.2 R18.2 v1(63.88,23.71) R20.2 ; SDO/SDA.1 37.72,22.83 38.87,23.97 U1.8
  BOTTOM w0.254: v1(64.64,18.87) 63.25,20.27 63.25,22.81 63.88,23.45 v1(63.88,23.71) 63.88,24.59 62.86,25.6 40,25.6 37.72,23.32 SDO/SDA.1
DAC_SYNCB: length 46.8
  TOP w0.254: PMOD.1 68.47,28.14 R24.1 65.14,29.16 58.42,29.16 55.5,26.24 55.5,15.06 54.61,14.17 50.93,14.17 46.54,9.79 R7.2 R10.1 R11.1
DAC_SYNCB/SCL: length 32.2
  TOP w0.254: R24.2 v1(63.88,28.14) ; 63.11,22.43 v1(63.88,22.43) ; 63.11,22.43 63.12,22.44 R26.2 ; 63.11,22.43 R25.2 ; SYNCB/SCL.1 48.92,26.87 48.62,26.58 U1.13
  BOTTOM w0.254: SYNCB/SCL.1 50.67,28.91 52.71,30.94 55.37,30.94 57.34,28.97 63.06,28.97 v1(63.88,28.14) 64.77,27.26 64.77,23.32 v1(63.88,22.43)
DAC_VDD: length 17.5
  TOP w0.305: 41.33,25.92 U1.5
  TOP w0.508: U3.2 C15.1 v1(56.42,38.35)
  L3_PWR w0.635: 65.82,37.95 VDD_SEL.2 ; VDD_SEL.2 65.82,39.72 ; VDD_SEL.2 67.6,39.72 ; VDD_SEL.2 67.6,37.95 ; VDD.1 59.04,47.09 ; VDD.1 57.36,45.41 ; VDD.1 59.04,45.41 ; VDD.1 57.36,47.09 ; 58.68,29.54 VDD_VIO.1 58.68,31.32
  vias: v1(43.6,32.77) v1(44.74,32.77)
DAC_VLOGIC: length 36.4
  TOP w0.254: C1.2 62.36,4.28 62.36,5.47 62.61,5.73 U4.8 ; R22.1 v1(60.96,28.14) ; U1.11 C12.1
  TOP w0.508: R7.1 v1(44.48,12.57) ; R4.1 v1(72.14,2.11) ; R32.1 v1(39.92,21.67) ; C1.2 v1(62.36,3.64) ; R29.1 v1(53.88,4.95) ; R5.2 v1(50.58,44.83) ; R9.1 v1(72.14,4.65) ; R1.1 v1(72.14,7.19) ; R31.1 v1(45.55,21.71)
  TOP w0.635: C12.1 v1(47.09,24.64)
  L3_PWR w0.635: 72.05,18.25 PMOD.12 ; PMOD.12 73.82,16.48 ; PMOD.12 73.82,18.25 ; PMOD.12 72.05,16.48 ; PMOD.6 71.28,16.48 ; PMOD.6 71.28,18.25 ; PMOD.6 69.51,16.48 ; PMOD.6 69.51,18.25 ; RSTSEL.1 64.26,35 ; RSTSEL.1 62.49,33.23 ; RSTSEL.1 64.26,33.23 ; VDD_VIO.2 62.99,31.32 ; VDD_VIO.2 61.22,31.32 ; VDD_VIO.2 62.99,29.54 ; VDD_VIO.2 61.22,29.54 ; VLOGIC.1 54.85,45.41 ; VLOGIC.1 53.17,47.09 ; VLOGIC.1 54.85,47.09 ; VLOGIC.1 53.17,45.41
DAC_VREF: length 8.8
  TOP w0.305: 40.93,28.96 40.5,28.52 U1.1
  L3_PWR w0.635: 34.37,47.09 VREF.1 ; VREF.1 36.05,47.09 ; VREF.1 36.05,45.41 ; VREF.1 34.37,45.41 ; 41.19,39.11 REF_SEL.2 41.19,37.34
  vias: v1(40.42,32.77) v1(41.44,32.77)
LDO_3V3: length 5.8
  TOP w0.635: VDD_SEL.3 65.06,39.72 ; VDD_SEL.3 65.06,37.95 ; VDD_SEL.3 63.28,37.95 ; VDD_SEL.3 63.28,39.72 ; C11.1 61.78,37.08
PMOD_SCLK/SDA: length 6
  TOP w0.254: PMOD.4 69.12,21.17 R28.1 R19.1
PMOD_SDO/SCL: length 6
  TOP w0.254: R26.1 R20.1 69.12,23.71 PMOD.3
UNNAMED_3_CAP_I47_N1: length 5
  TOP w0.635: C2.1 40.86,47.81 E1.1
  TOP w0.762: P3.5 E1.1
UNNAMED_3_CN8PA_I4_N2: length 3.3
  TOP w0.635: R5.1 P3.2
UNNAMED_3_CN10P_I1_N2: length 3.6
  TOP w0.254: R11.2 P6.2
UNNAMED_3_CN10P_I1_N3: length 3.6
  TOP w0.254: R10.2 P6.3
UNNAMED_3_FERRITE_I48_N2: length 1.7
  TOP w0.508: R6.1 42.96,43.19 E1.2
UNNAMED_3_IC24FC256_I22_A1: length 3.6
  TOP w0.254: U4.2 69.26,6.38 R2.1 R9.2
UNNAMED_3_IC24FC256_I22_A2: length 3.5
  TOP w0.254: R8.1 R1.2 69.56,7.03 U4.3
UNNAMED_3_RES_I15_N1: length 5.4
  TOP w0.254: R4.2 R12.1 69.22,3.38 68.96,3.63 68.96,5.41 68.65,5.73 U4.1
VREF_2V5: length 6.3
  TOP w0.254: U3.6 U3.7 C18.1 REF_SEL.3
VREF_EXT: length 6.2
  TOP w0.254: EXT_REF.1 REF_SEL.1

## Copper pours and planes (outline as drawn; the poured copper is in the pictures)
AGND on TOP: 0.64,51.82 19.34,51.82 19.34,46.1 61.12,46.1 61.12,50.42 67.6,50.42 67.6,21.67 57.69,21.67 57.69,4.06 16.42,4.06 16.42,0.63 0.64,0.63
AGND on BOTTOM: 0.64,51.82 19.34,51.82 19.34,46.1 61.12,46.1 61.12,50.42 67.6,50.42 67.6,14.1 57.69,14.1 57.69,4.06 16.42,4.06 16.42,0.63 0.64,0.63
AGND on L2_GND: 0.64,51.82 19.34,51.82 19.34,46.1 29.77,46.1 30.73,47.07 31.5,47.07 32.46,46.1 61.12,46.1 61.12,50.42 67.6,50.42 67.6,14.1 57.69,14.1 57.69,4.06 16.42,4.06 16.42,0.63 0.64,0.63
AGND on L3_PWR: 0.64,51.82 19.34,51.82 19.34,46.1 61.12,46.1 61.12,50.42 67.6,50.42 67.6,14.1 57.69,14.1 57.69,3.89 16.42,3.89 16.42,0.63 0.64,0.63
DGND on TOP: 7.78,0.71 7.78,51.87 77.09,51.87 77.09,0.71
DGND on BOTTOM, L2_GND, L3_PWR: 7.78,0.63 7.78,51.87 76.11,51.87 76.11,0.63
VBUS_USB on TOP: 60.87,44.07 60.87,40.39 61.88,40.39 61.88,42.54 62.14,42.8 62.14,43.81 61.88,44.07
VBUS_USB on L3_PWR: 47.66,44.07 47.66,39.7 60.82,39.7 62.26,41.15 62.26,44.07
VDD_EXT on TOP: 68.36,50.29 68.36,37.21 71.66,37.21 71.66,50.29
DAC_VDD on TOP: 43.09,32.77 43.09,30.1 41.94,28.96 41.94,26.78 41.28,26.11 40.75,26.11 40.67,26.04 40.67,25.78 42.59,25.78 43.31,26.49 43.31,28.27 44.2,29.16 44.2,30.7 44.36,30.86 45.12,30.86 45.25,30.99 45.25,32.77 44.87,33.15 43.47,33.15
DAC_VDD on L3_PWR: 59.1,25.78 42.96,25.78 42.96,39.12 61.01,39.12 62.86,40.97 62.86,44.58 56.68,44.58 56.68,47.7 66.5,47.7 68.23,45.97 68.23,37.46 67.04,36.27 64.52,36.27 60.2,31.95 60.2,26.87
DAC_VLOGIC on L3_PWR: 47.66,51.87 76.11,51.87 76.11,47.72 75.73,47.34 76.11,47.34 76.11,46.45 75.85,46.45 76.11,46.19 76.11,35.02 75.73,34.64 76.11,34.64 76.11,33.87 75.73,33.87 76.11,33.49 76.11,22.32 75.85,22.06 76.11,22.06 76.11,21.05 75.85,21.05 76.11,20.79 76.11,15.21 75.85,14.95 76.11,14.95 76.11,14.06 75.73,14.06 76.11,13.68 76.11,9.62 75.85,9.36 76.11,9.36 76.11,8.47 75.73,8.47 76.11,8.09 76.11,0.97 61.98,0.97 61.98,3.89 29.63,3.89 29.63,25.27 59.36,25.27 60.71,26.62 60.71,31.95 65.15,36.4 67.31,36.4 68.07,37.16 68.07,46.81 66.88,48.01 56.17,48.01 56.17,44.45 47.66,44.45
DAC_VREF on TOP: 41.94,33.15 42.07,33.02 42.07,30.86 41.56,30.35 41.56,28.83 41.31,28.57 40.67,28.57 40.67,29.21 40.55,29.34 40.55,30.48 39.79,31.24 39.79,33.02 39.91,33.15
DAC_VREF on L3_PWR: 29.37,32.26 42.42,32.26 42.42,39.7 47.15,39.7 47.15,51.87 29.37,51.87
LDO_3V3 on TOP: 60.74,39.62 60.74,36.58 64.3,36.58 65.44,37.72 65.44,40.13 63.03,40.13 62.52,39.62

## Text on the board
BOTTOM: SECONDARY SIDE | 08-070413 REV A Z
Ref Des/Silkscreen Bottom: 08-069100 REV A Z | SECONDARY SIDE
User.Comments: SEE NOTE 10 | 10.    APPLY STICKER LABEL TO BOX ACCORDING TO BOM VARIANT DECLARATION: | 8.   DO NOT TRIM EXCESS PINS OF THE FOLLOWING LOCATIONS: | 7.    INSTALL JUMPER SHUNTS (M029337) ON THE FOLLOWING LOCATIONS: | 9.    SHIPMENT WILL INCLUDE STANDOFFS(M025474) AND SCREWS(M025339). | 5.    BOARDS TO BE SHIPPED SINGULATED AFTER ASSEMBLY PROCESS. | 6.    SMOOTHEN EDGES AND FREE FROM BURRS AFTER DEPANELIZATION PROCESS. | 4.    RoHS COMPLIANCE: ASSEMBLY VENDOR SHOULD ASSURE COMPLIANCE | B. P3 | A. P4 | C. P6 | D. P7 | * EVAL-AD5696RARDZ FOR 05-070413-02 | * EVAL-AD5686RARDZ FOR 05-070413-01 | A. VDD_SEL (PIN 2-3) | WITH LEAD-FREE AND RoHS PCB ASSEMBLY STANDARDS (EU RoHS | DIRECTIVE 2002/95/EC). | B. REF_SEL (PIN 1-2) | C. VDD_VIO (PIN1) | D. RSTSEL (PIN 1-2)
Ref Des/Assembly Top: EVAL- | +
Ref Des/Silkscreen Top: EVAL- | PRIMARY SIDE | 08-070413 REV B Z | SCLK/SDA | VIO | DGND | SDIN | SYNCB | SDO/SCL | GAIN | LDACB | RESETB | RSTSEL | EXT | 2V5 | GND | 3V3 | VDD
XSECTION_CHART: *  SURFACE | * SOLDERMASK_TOP MASK | L1 TOP CONDUCTOR | *  DIELECTRIC | L2 L2_GND PLANE | L3 L3_PWR PLANE | L4 BOTTOM CONDUCTOR | * SOLDERMASK_BOTTOM MASK | DESIGN CROSS SECTION CHART | ___________________________ | TOTAL THICKNESS 62 MIL | 1-4
PAGE_OUTLINE: 1 | 09FEB22 | B | CHANGES AS PER ECR-114918 | 12JUL23 | D.DALISAY | EVAL-AD5686RARDZ
DIMENSION: " " | (REF) | NON PLATED: +/- 2MILS | DIA MAX
User.6: ROHS COMPLIANCE NOTE: | ISOLA370HR OR S1000-2 OR IT180 OR EQUIVALENT. | HOMOGENOUS MATERIALS IN THIS BOARD SHALL BE COMPLIANT | THE EU RoHS DIRECTIVE 2002/95/EC | SECONDARY SILKSCREEN | 16.    PANEL TO BE SUBJECTED TO CUSTOMER'S APPROVAL. | 17.    PANELED SOLDER PASTE STENCIL SHOULD BE SENT TO THE CUSTOMER. | 15.    BOARDS TO BE SHIPPED IN ARRAY AND KEEP INTACT.
User.14: L2 GND | 08-      -07
User.15: L3 PWR | 08-      -08
User.16: L4 GND | 08-      -09
User.17: L5 PWR | 08-      -10
User.21: L2 GND | 08-      -06
User.22: L3 PWR | 08-      -07
User.27: M.BELAID | J.MORIN | 17AUG15 | 24355
User.34: FIGURE | SIZE | 10.0 | 40.0 | 45.0 | 46.0 | 50.0 | 60.0 | 67.0 | 125.0 | DRILL CHART: TOP to BOTTOM | FINISHED HOLES IN MILS | PLATED | NON-PLATED | QTY | 263 | 17 | 55 | 1 | 6 | 16 | 4 | TOLERANCE/NOTES
